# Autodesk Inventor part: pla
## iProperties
Author: chr
Shininess: 20.0
PropertySet Name: _Private Model Information
Length Units: 11269
Angle Units: 11286
Time Units: 11279
Mass Units: 11290
Length Display Precision: 3
Angle Display Precision: 2
Compacted: False
Created: 2001-06
Part Number: pla
Material: Par défaut
Document SubType Name: Modélisation
Designer: chr
Control State: 0
Master: False
Checked Out: False
PropertySet Name: Design Tracking Control
Density: 0.0
Volumn: 0.0
Area: 0.0
PropertySet Name: Model Information
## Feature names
1. Extrusion1
2. Extrusion2
3. Extrusion3
4. Perçage1 [Hole]
5. Congé1 [Fillet]
6. Congé2 [Fillet]
7. Extrusion4
8. Perçage2 [Hole]
